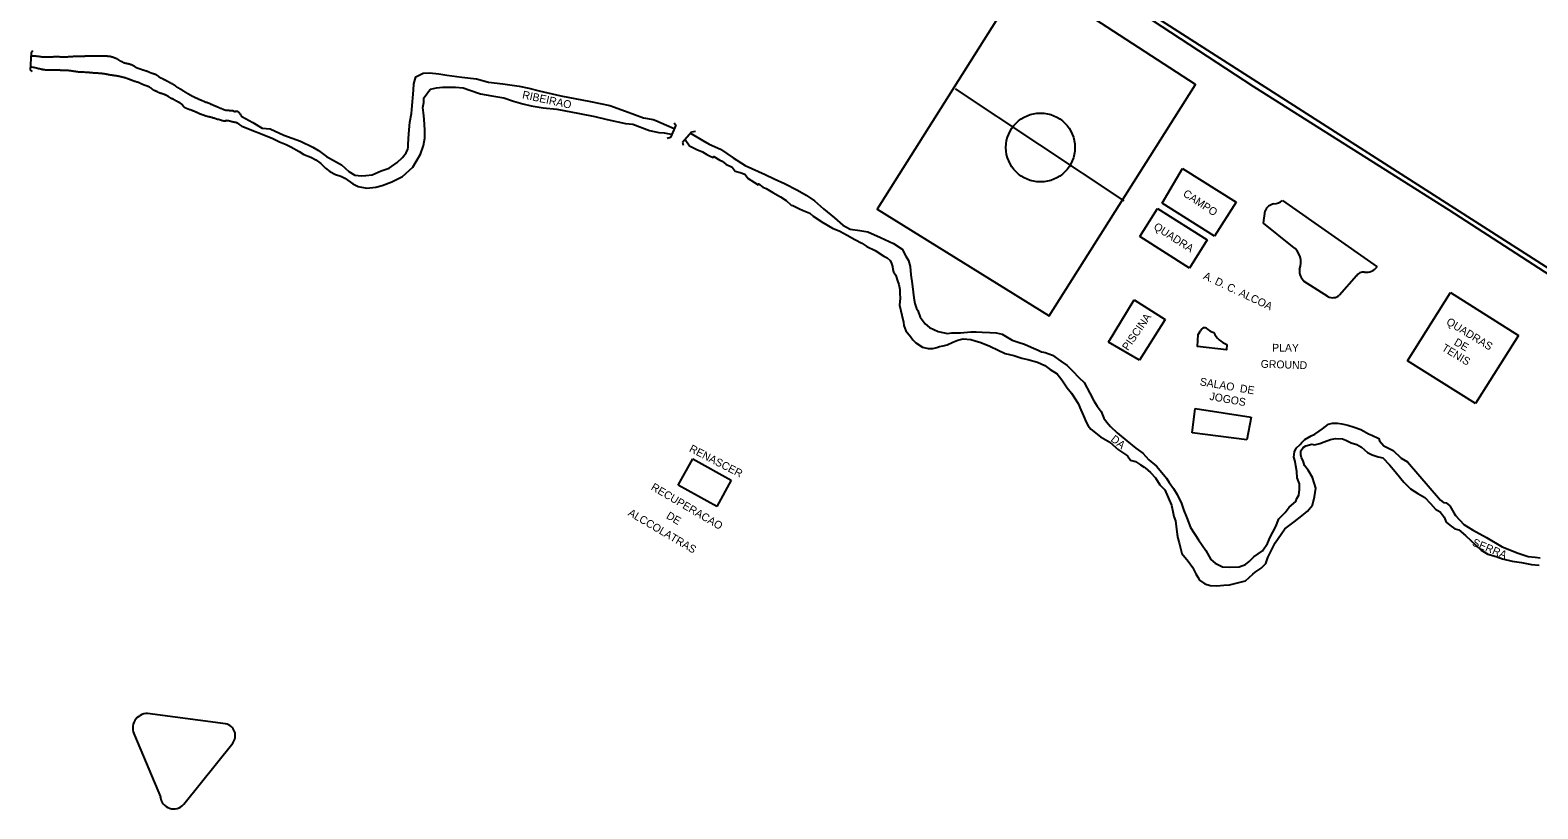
# Model space of a CAD drawing. Extents: x 325899 to 364828, y 7568995 to 7592502.
# Drawn here: x 341573 to 342345, y 7589058 to 7589457 of the extents above; entities that cross this region are included whole.
import ezdxf

# ---------------------------------------------------------------- set-up
doc = ezdxf.new("R2010")
doc.units = 0
for name, color, linetype in [('EDIFEXISTENT', 7, 'Continuous'), ('EDIFIDENTIF', 7, 'Continuous'), ('EDIFOBRAEXIS', 7, 'Continuous')]:
    doc.layers.add(name, color=color, linetype=linetype)

msp = doc.modelspace()

# ---------------------------------------------------------------- linework, layer by layer
at = {"layer": 'EDIFEXISTENT'}
for p, q in [((341574.25, 7589445.99), (341573.34, 7589445.08)), ((341573.34, 7589445.08), (341572.87, 7589436.16)), ((341572.87, 7589436.16), (341573.89, 7589435.5)), ((341903.8, 7589407.85), (341901, 7589401.69)), ((341902.92, 7589409.13), (341903.8, 7589407.85)), ((341901, 7589401.69), (341899.33, 7589401.16)), ((341911.7, 7589404.36), (341907.14, 7589398.96)), ((341907.14, 7589398.96), (341907.56, 7589397.6)), ((341913.81, 7589404.64), (341911.7, 7589404.36)), ((342152.88, 7589367.94), (342163.28, 7589385.77)), ((342163.28, 7589385.77), (342190.81, 7589368.45)), ((342179.82, 7589350.99), (342152.88, 7589367.94)), ((342190.81, 7589368.45), (342179.82, 7589350.99)), ((342141.52, 7589350.87), (342150.53, 7589365.19)), ((342150.53, 7589365.19), (342176.04, 7589349.14)), ((342166.9, 7589334.61), (342141.52, 7589350.87)), ((342176.04, 7589349.14), (342166.9, 7589334.61)), ((342278.67, 7589287.14), (342300.64, 7589322.17)), ((342300.64, 7589322.17), (342335.54, 7589300.21)), ((342125.42, 7589296.72), (342138.53, 7589318.45)), ((342138.53, 7589318.45), (342154.55, 7589308.4)), ((342154.55, 7589308.4), (342141.37, 7589287.45)), ((342335.54, 7589300.21), (342313.52, 7589265.21)), ((342141.37, 7589287.45), (342125.42, 7589296.72)), ((342313.52, 7589265.21), (342278.67, 7589287.14)), ((342168.39, 7589250.32), (342169.89, 7589262.69)), ((342169.89, 7589262.69), (342198.52, 7589258.27)), ((342198.52, 7589258.27), (342196.29, 7589246.68)), ((342196.29, 7589246.68), (342168.39, 7589250.32)), ((341904.9, 7589223.47), (341912.48, 7589236.94)), ((341912.48, 7589236.94), (341932.14, 7589226.06)), ((341924.66, 7589212.53), (341904.9, 7589223.47)), ((341932.14, 7589226.06), (341924.66, 7589212.53))]:
    msp.add_line(p, q, dxfattribs=at)
at = {"layer": 'EDIFOBRAEXIS'}
for points in [[(342446.11, 7589269.87), (342299.94, 7589364.31), (342199.85, 7589427.54), (342086.62, 7589501.91)], [(342092.03, 7589501.91), (342154.85, 7589460.08), (342361.94, 7589327.42), (342447.7, 7589272.56)], [(342082.91, 7589485.44), (342006.92, 7589364.96), (342094.99, 7589310.3), (342169.93, 7589428.74), (342082.91, 7589485.44)], [(341681.39, 7589412.42), (341686.97, 7589409.25), (341691.71, 7589406.46), (341695.78, 7589406.02), (341702.86, 7589402.83), (341711.36, 7589399.68), (341717.73, 7589396.6), (341720.55, 7589394.9), (341724.75, 7589391.95), (341732.33, 7589387.62), (341736.13, 7589384.11), (341739.3, 7589382.31), (341742.74, 7589382.02), (341744.9, 7589382.05), (341748.1, 7589382.49), (341751.28, 7589383.83), (341752.78, 7589384.45), (341756.9, 7589385.85), (341760.99, 7589388.72), (341763.63, 7589391.29), (341765.63, 7589393.68), (341766.35, 7589395.65), (341766.59, 7589396.59), (341766.57, 7589398.12), (341766.91, 7589403.43), (341767.45, 7589409.52), (341768.24, 7589413.87), (341768.49, 7589416.04), (341769.34, 7589425.81), (341769.41, 7589429.14), (341770.56, 7589432.71), (341774.22, 7589434.51), (341777.43, 7589434.67), (341782.34, 7589434.27), (341786.46, 7589433.56), (341794.05, 7589432.48), (341801.64, 7589431.65), (341807.68, 7589430.02), (341815.09, 7589429.14), (341823.47, 7589427.87), (341828.33, 7589426.89), (341833.74, 7589425.55), (341844.85, 7589422.96), (341860.04, 7589420.14), (341869.9, 7589418.07), (341877.86, 7589415.12), (341887.08, 7589411.74), (341892.1, 7589410.79), (341893.5, 7589410.29), (341899, 7589407.97), (341902.88, 7589406.24)], [(341681.39, 7589407.44), (341696.93, 7589401.26), (341700.69, 7589399.37), (341704.09, 7589397.96), (341706.52, 7589396.75), (341710.74, 7589394.46), (341713.05, 7589392.86), (341716.67, 7589391.55), (341719.28, 7589390.08), (341721.74, 7589388.26), (341724.26, 7589385.95), (341726.49, 7589384.14), (341729.33, 7589382.63), (341732.01, 7589381.72), (341734.19, 7589380.8), (341738.16, 7589377.9), (341741, 7589376.41), (341745.38, 7589375.62), (341750, 7589376.14), (341753.27, 7589376.96), (341758.26, 7589378.83), (341763.71, 7589381.66), (341768.92, 7589386.45), (341770.74, 7589389.32), (341772.93, 7589393.11), (341774.46, 7589397.52), (341775.15, 7589401.19), (341775.15, 7589405.44), (341774.78, 7589411.05), (341774.49, 7589414.2), (341774.05, 7589417.02), (341774.53, 7589419.46), (341774.65, 7589421.9), (341775.73, 7589423.52), (341777.06, 7589425.14), (341778.01, 7589426.29), (341781.1, 7589427.09), (341784.09, 7589427.46), (341787.65, 7589427.47), (341790.81, 7589427.46), (341794.7, 7589427), (341798.22, 7589425.94), (341803.61, 7589424), (341809.37, 7589422.92), (341815.58, 7589422.01), (341820.61, 7589420.31), (341825.25, 7589418.94), (341829.59, 7589417.75), (341835.72, 7589416.88), (341842.67, 7589416.05), (341854.42, 7589413.87), (341862.19, 7589412.39), (341868.56, 7589410.81), (341878.02, 7589408.76), (341881.76, 7589408.37), (341890.18, 7589405.22), (341894.95, 7589404.16), (341897.8, 7589403.99), (341899.46, 7589403.58), (341901.59, 7589403.3)], [(342046.8, 7589426.61), (342133.27, 7589369.1)], [(341908.55, 7589400.63), (341910.79, 7589397.41), (341912.79, 7589396.23), (341914.5, 7589395.44), (341917.31, 7589394.28), (341919.61, 7589392.93), (341920.92, 7589392.14), (341922.83, 7589391.37), (341922.86, 7589391.52), (341923.19, 7589391.83), (341926.36, 7589389.99), (341927.46, 7589389.47), (341929.33, 7589387.99), (341932.65, 7589386.43), (341934.05, 7589384.41), (341936.73, 7589383.63), (341939.08, 7589382.74), (341940.73, 7589380.65), (341942.11, 7589379.8), (341945.85, 7589377.31), (341946.15, 7589377.84), (341948.23, 7589376.16), (341950.07, 7589375.45), (341953.42, 7589373.43), (341957.42, 7589371.16), (341960.21, 7589369.34), (341962.88, 7589367.01), (341963.6, 7589366.79), (341966.79, 7589365.28), (341968.99, 7589364.16), (341971.52, 7589363.17), (341972.36, 7589362.75), (341974.03, 7589361.22), (341979.05, 7589358.12), (341984.04, 7589355.13), (341987.77, 7589353.6), (341991.56, 7589351.64), (341995.45, 7589349.37), (341999.06, 7589347.53), (342001.57, 7589345.83), (342005.89, 7589343.67), (342010.35, 7589340.78), (342011.96, 7589339.88), (342013.55, 7589338.55), (342014.18, 7589336.98), (342014.68, 7589335.57), (342014.9, 7589334.02), (342015.3, 7589332.7), (342016.26, 7589331.19), (342016.65, 7589330.3), (342017.26, 7589328.12), (342017.94, 7589326.33), (342018.43, 7589323.71), (342018.55, 7589321.73), (342018.71, 7589319.27), (342018.4, 7589315.73), (342019.52, 7589310.63), (342020.33, 7589307.01), (342020.55, 7589305.18), (342021.6, 7589302.52), (342024, 7589299.6), (342025.24, 7589297.91), (342026.76, 7589296.31), (342030.17, 7589294.16), (342033, 7589293.48), (342035.36, 7589293.48), (342037.49, 7589293.99), (342038.78, 7589294.54), (342040.71, 7589294.79), (342042.79, 7589295.38), (342045.69, 7589296.73), (342048.25, 7589297.73), (342050.99, 7589298.47), (342054.85, 7589298.06), (342057.15, 7589297.43), (342059.96, 7589296.47), (342064.68, 7589294.67), (342068.82, 7589292.58), (342072.4, 7589290.92), (342076.89, 7589289.81), (342081, 7589288.51), (342084.08, 7589287.78), (342089.13, 7589286.52), (342092.76, 7589284.78), (342095.48, 7589282.73), (342099.07, 7589280.46), (342101.57, 7589277.36), (342104.21, 7589273.4), (342106.4, 7589270.56), (342109.92, 7589265.28), (342111.23, 7589262), (342112.69, 7589259.01), (342114.02, 7589255.8), (342115.01, 7589253.78), (342116.43, 7589252.17), (342121.38, 7589248.21), (342126.04, 7589245.47), (342130.59, 7589241.58), (342135.25, 7589238.41), (342136.78, 7589236.24), (342139.25, 7589235.56), (342141.86, 7589233.94), (342143.79, 7589232.66), (342144.3, 7589232.34), (342146.94, 7589230.01), (342149.6, 7589227.19), (342151.7, 7589223.53), (342154.24, 7589221.04), (342157.67, 7589213.23), (342158.5, 7589209.17), (342158.93, 7589207.42), (342159.72, 7589205.14), (342160.67, 7589198.14), (342160.97, 7589196.29), (342161.66, 7589193.9), (342163.07, 7589188.46), (342166.19, 7589184.43), (342168.49, 7589181.38), (342170.18, 7589177.99), (342171.17, 7589176.22), (342172.05, 7589174.76), (342174.87, 7589172.89), (342177.45, 7589172.05), (342181.03, 7589171.79), (342184.51, 7589172.16), (342187.43, 7589172.42), (342195.65, 7589174.4), (342199.39, 7589177.85), (342200.65, 7589178.81), (342203.6, 7589180.9), (342206.12, 7589183.3), (342207.12, 7589186.43), (342208.64, 7589189.45), (342210.9, 7589193.8), (342213.95, 7589198.34), (342215.82, 7589201.03), (342220.5, 7589204.72), (342224.56, 7589207.79), (342227.41, 7589210.09), (342229.89, 7589213.14), (342231.03, 7589217.48), (342231.59, 7589221.91), (342230.05, 7589227.43), (342227.72, 7589231.04), (342225.88, 7589233.51), (342225.22, 7589235.94), (342224.41, 7589237.4), (342223.99, 7589238.97), (342224.04, 7589241.03), (342225.16, 7589242.78), (342226.53, 7589243.61), (342229.7, 7589244.43), (342230.94, 7589244.17), (342233.66, 7589244.81), (342235.96, 7589245.6), (342239.2, 7589246.86), (342241.69, 7589247.32), (342245.3, 7589247.16), (342247.06, 7589246.47), (342249.85, 7589245.18), (342252.63, 7589244.3), (342255.01, 7589242.95), (342256.65, 7589241.6), (342258.19, 7589240.12), (342260.54, 7589238.95), (342263.63, 7589238.02), (342266.03, 7589237.46), (342269.43, 7589233.92), (342270.41, 7589232.63), (342273.04, 7589229.54), (342276.72, 7589225.01), (342280.25, 7589221.57), (342284.01, 7589219.2), (342287.57, 7589217.15), (342290.48, 7589214.04), (342292.98, 7589211.22), (342295.31, 7589209.72), (342297.4, 7589207), (342298.52, 7589204.52), (342300.32, 7589202.94), (342302.89, 7589201.09), (342304.95, 7589200.48), (342308.39, 7589197.57), (342316.41, 7589190.17), (342319.89, 7589188.1), (342324.05, 7589186.8), (342327.32, 7589185.77), (342332.21, 7589184.43), (342334.66, 7589184.23), (342337.03, 7589183.8), (342342.12, 7589182.77), (342346.19, 7589182.41)], [(341911.3, 7589403.88), (341917.62, 7589400), (341920.75, 7589398.26), (341926.55, 7589395.71), (341933.06, 7589391.26), (341939.2, 7589387.34), (341949.48, 7589382.66), (341954.1, 7589380.43), (341959.44, 7589378.1), (341966.15, 7589374.67), (341970.52, 7589372.13), (341974.75, 7589369.16), (341979.43, 7589365.12), (341984.95, 7589360.51), (341989.29, 7589356.69), (341993.12, 7589354.68), (341998.06, 7589353.95), (342002.17, 7589353.26), (342008.61, 7589350.42), (342015.33, 7589347.24), (342019.71, 7589344.37), (342021.66, 7589340.78), (342022.96, 7589338.51), (342023.73, 7589335.42), (342024.19, 7589331.23), (342024.9, 7589326.53), (342025.36, 7589322.27), (342025.67, 7589319.48), (342026.24, 7589316.48), (342027.03, 7589314.03), (342027.73, 7589312.89), (342028.92, 7589309.55), (342031.45, 7589306.05), (342033.71, 7589304.22), (342038.13, 7589302.19), (342042.92, 7589301.23), (342044.95, 7589301.43), (342049.6, 7589301.58), (342054.83, 7589302), (342057.55, 7589302.08), (342060.71, 7589301.92), (342064.65, 7589301.69), (342067.83, 7589301.42), (342071.01, 7589300.77), (342076.06, 7589297.83), (342079.61, 7589296.5), (342082.44, 7589295.67), (342085.84, 7589294.21), (342089.39, 7589292.55), (342091.13, 7589291.7), (342092.15, 7589291.59), (342092.96, 7589291.5), (342096.66, 7589289.99), (342101.02, 7589287.02), (342104.33, 7589284.74), (342106.93, 7589282.05), (342110.17, 7589278.66), (342112.97, 7589276.05), (342115.81, 7589270.62), (342117.99, 7589266.63), (342119.65, 7589263.9), (342121.66, 7589261.18), (342123, 7589257.81), (342124.39, 7589255.95), (342126.43, 7589253.53), (342129.93, 7589250.32), (342134.75, 7589246.21), (342139.43, 7589242.32), (342143.04, 7589239.85), (342146.13, 7589236.48), (342149.98, 7589233.09), (342151.84, 7589230.9), (342154.29, 7589228.03), (342155.09, 7589227.05), (342156.59, 7589224.78), (342158.71, 7589221.71), (342160.7, 7589218.63), (342162.82, 7589214.03), (342164.11, 7589210.43), (342165.5, 7589206.76), (342167.49, 7589201.73), (342171.48, 7589195.47), (342175.3, 7589190), (342177.95, 7589185.4), (342180.08, 7589183.52), (342183.82, 7589181.66), (342187.45, 7589181.42), (342192.36, 7589181.61), (342195.6, 7589182.71), (342197.44, 7589184.31), (342199.9, 7589186.65), (342204.36, 7589189.71), (342206.96, 7589193.47), (342208.32, 7589196.79), (342209.66, 7589199.4), (342211.13, 7589202.32), (342212.71, 7589206.13), (342214.34, 7589207.92), (342215.98, 7589209.37), (342218.08, 7589212.24), (342221.37, 7589215.05), (342221.86, 7589216.66), (342222.94, 7589218.32), (342223.23, 7589221.25), (342223.25, 7589224.07), (342222.12, 7589227.26), (342222.01, 7589230.46), (342221.44, 7589233.38), (342221.06, 7589235.61), (342220.44, 7589237.87), (342220.77, 7589240.49), (342221.66, 7589242.48), (342223.77, 7589244.41), (342224.35, 7589245.21), (342226.11, 7589246.88), (342229.29, 7589248.75), (342231.11, 7589249.58), (342233.46, 7589251.03), (342235.17, 7589252.3), (342238.24, 7589254.65), (342240.24, 7589255.28), (342242.76, 7589255.21), (342244.93, 7589254.88), (342248.14, 7589254.21), (342251.28, 7589253.23), (342254.7, 7589252.05), (342256.31, 7589251.15), (342258.64, 7589249.71), (342260.32, 7589249.06), (342263.9, 7589247.38), (342264.32, 7589246.14), (342266.44, 7589243.62), (342271.3, 7589241.16), (342275.33, 7589237.27), (342278.58, 7589235.4), (342295.64, 7589215.8), (342297.13, 7589214.57), (342298.43, 7589214.33), (342300.31, 7589212.88), (342302.43, 7589209.22), (342303.26, 7589207.91), (342307.49, 7589203.36), (342312.02, 7589200.61), (342319.06, 7589196.55), (342327.22, 7589191.77), (342335.39, 7589188.54), (342340.47, 7589186.94), (342344.01, 7589186.48), (342346.61, 7589186.18)], [(342214.52, 7589369.25), (342263.07, 7589335.35)], [(342219.78, 7589345.81), (342204.82, 7589357.77), (342205.68, 7589364.08)], [(342252.47, 7589330.64), (342243.87, 7589320.81)], [(342237.75, 7589320.05), (342225.74, 7589327.84)], [(342186.1, 7589295.57), (342185.86, 7589292.82), (342171.09, 7589294.43), (342171.33, 7589300.61), (342172.62, 7589302.45)], [(341673.03, 7589101.17), (341633.06, 7589106.44)], [(341626.36, 7589095.26), (341639.58, 7589063.7)], [(341651.54, 7589059.89), (341676.69, 7589091.22)]]:
    msp.add_lwpolyline(points, dxfattribs=at)
msp.add_circle((342090.56, 7589396.49), 17.67, dxfattribs=at)
for centre, radius, start, end in [((342209.43, 7589375.83), 8.32, 275.18931, 307.66108), ((342210.86, 7589362.01), 5.57, 96.90516, 158.21298), ((342214.17, 7589337.7), 9.87, 337.75249, 55.29546), ((342230.8, 7589333.4), 7.52, 175.72742, 227.67019), ((342255.96, 7589328.73), 3.97, 80.46904, 151.43309), ((342257.62, 7589339.32), 6.74, 261.422, 323.922), ((342240.21, 7589325.22), 5.73, 244.5081, 309.63096), ((342174.6, 7589302.04), 2.02, 65.02252, 168.07668), ((342184.4, 7589315.01), 14.28, 231.23968, 249.61895), ((342189.59, 7589306.14), 11.13, 203.9592, 251.73883), ((341633.01, 7589098.87), 7.57, 89.58459, 208.55733), ((341671.75, 7589095.05), 6.25, 322.19329, 78.19944), ((341646.39, 7589064.41), 6.85, 185.94, 318.7253)]:
    msp.add_arc(centre, radius, start, end, dxfattribs=at)
for points in [[(341572.97, 7589437.97), (341577.28, 7589436.98), (341577.66, 7589436.98), (341579.21, 7589436.45), (341582.96, 7589436.17), (341585.36, 7589436.28), (341586.43, 7589436.25), (341586.86, 7589436.23), (341587.8, 7589436.21), (341589.09, 7589436.18), (341591.85, 7589436.21), (341597.22, 7589435.33), (341598.97, 7589435.23), (341602.19, 7589435.11), (341604.52, 7589434.86), (341606.19, 7589434.78), (341607.74, 7589434.68), (341609.21, 7589434.53), (341610.15, 7589434.46), (341611.67, 7589434.23), (341612.93, 7589433.96), (341614.13, 7589433.7), (341615.06, 7589433.63), (341616.03, 7589433.45), (341617.75, 7589433.23), (341620.77, 7589432.52), (341622.13, 7589432.14), (341624.87, 7589431.08), (341626.22, 7589430.53), (341628.4, 7589429.97), (341629.69, 7589429.24), (341632.76, 7589428.08), (341633.59, 7589427.8), (341634.58, 7589427.14), (341636.13, 7589425.95), (341637.22, 7589425.5), (341639.3, 7589424.49), (341639.73, 7589424.41), (341641.3, 7589423.93), (341641.88, 7589423.66), (341643.63, 7589422.77), (341644.88, 7589421.84), (341645.97, 7589421.46), (341646.83, 7589420.93), (341648.2, 7589420.19), (341649.31, 7589419.61), (341649.82, 7589419.28), (341650.68, 7589418.62), (341651.62, 7589417.18), (341652.99, 7589416.6), (341655.3, 7589415.77), (341657.4, 7589414.93), (341659.05, 7589414.18), (341659.51, 7589413.95), (341661.74, 7589413.14), (341663.03, 7589412.64), (341665.44, 7589412.13), (341668.86, 7589411.07), (341672.59, 7589410.04), (341672.84, 7589410.24), (341674.61, 7589410.34), (341676.84, 7589409.59), (341678.24, 7589409.51), (341679.15, 7589409.06), (341679.97, 7589408.45), (341681.39, 7589407.44)], [(341573.26, 7589443.53), (341576.89, 7589443.39), (341579.1, 7589442.86), (341582.29, 7589442.89), (341584.95, 7589443.04), (341585.66, 7589443.12), (341587.94, 7589443.05), (341589.89, 7589442.9), (341593.19, 7589443.08), (341594.93, 7589443.21), (341596.99, 7589443.34), (341597.37, 7589443.36), (341600.46, 7589443.34), (341603.45, 7589443.47), (341604.87, 7589443.4), (341608.13, 7589443.48), (341610.79, 7589443.48), (341614.27, 7589443.28), (341617.31, 7589442.05), (341619.01, 7589440.88), (341619.69, 7589440.63), (341620.86, 7589439.92), (341624.71, 7589439.19), (341627.25, 7589437.42), (341628.54, 7589437.04), (341631.2, 7589436.13), (341633.13, 7589435.53), (341634.62, 7589434.8), (341637.31, 7589434.04), (341639.24, 7589432.44), (341641.9, 7589431.23), (341644.94, 7589429.56), (341647.05, 7589428.35), (341648.04, 7589427.51), (341650.47, 7589426.15), (341653.31, 7589424.33), (341657.24, 7589422.23), (341660.16, 7589420.92), (341663, 7589419.78), (341666.6, 7589418.29), (341668.32, 7589417.56), (341670.27, 7589416.72), (341672.73, 7589415.69), (341673.87, 7589415.59), (341674.25, 7589415.61), (341674.88, 7589415.54), (341675.8, 7589415.36), (341676.23, 7589415.39), (341676.63, 7589415.44), (341677.64, 7589414.88), (341678.6, 7589415.18), (341679.44, 7589415.05), (341681.39, 7589412.42)]]:
    msp.add_open_spline(points, degree=2, dxfattribs=at)

# ---------------------------------------------------------------- texts
at = {"layer": 'EDIFIDENTIF'}
for s, rotation, p in [('RIBEIRAO', 347.78288, (341824.77, 7589421.75)), ('CAMPO', 326.5415, (342163.24, 7589371.91)), ('QUADRA', 327.17256, (342148.2, 7589354.94)), ('A. D. C. ALCOA', 334.591, (342173.62, 7589329.35)), ('PISCINA', 55.39979, (342135.38, 7589292.1)), ('QUADRAS', 328.54125, (342298.15, 7589306.14)), ('DE', 329.95487, (342302.11, 7589295.59)), ('PLAY', 359.82629, (342209.29, 7589291.87)), ('TENIS', 328.73437, (342295.81, 7589292.74)), ('GROUND', 358.17207, (342203.4, 7589283.64)), ('SALAO  DE', 350.4618, (342172.02, 7589274.64)), ('JOGOS', 349.86116, (342176.97, 7589267.19)), ('DA', 321.56512, (342126.24, 7589246.34)), ('RENASCER', 332.73898, (341910.23, 7589240.88)), ('RECUPERACAO', 329.52354, (341890.63, 7589221.35)), (' ALCCOLATRAS', 329.52354, (341877.6, 7589208.94)), ('DE', 329.52354, (341898.46, 7589206.68)), ('SERRA', 337.76452, (342311.53, 7589192.55))]:
    msp.add_text(s, height=4, rotation=rotation, dxfattribs=at).set_placement(p)

doc.saveas('drawing.dxf')
